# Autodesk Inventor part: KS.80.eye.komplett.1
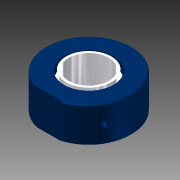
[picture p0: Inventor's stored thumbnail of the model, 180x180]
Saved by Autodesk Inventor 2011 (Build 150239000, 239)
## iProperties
Created: 2010-11
Part Number: KS.80.eye.komplett.1
Document SubType Name: Modeling
Designer: tribel
Density: 1 g/cm^3
Author: tribel
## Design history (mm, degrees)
derived "KS80eye.iam"
body "Solid1"
node "Lagerhus80.ipt:1"
node "Kule80HO.ipt:1"
sketch "Smørenippel.ipt:1"
